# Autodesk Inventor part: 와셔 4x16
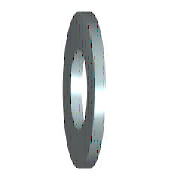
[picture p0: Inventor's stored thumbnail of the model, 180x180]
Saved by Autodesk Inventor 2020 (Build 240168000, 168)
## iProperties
IsCustomPart: 1
Created: 2012-02
Part Number: 와셔 4x16
Material: 강철, 연강
Description: 미터법 평면 와셔
Document SubType Name: Modeling
Standard: ANSI B18.22M
Designer: mduedu
Standard Revision: 1999
Standards Organization: ANSI
Language: ko-KR
Size Designation: 4 W
Categories: <MemberInstance><Categories><Category DisplayName="조임쇠" InternalName="e4da775c-781d-43d5-af7c-5136215cf5a6" Mnemonic="FSTN"><Category DisplayName="와셔" InternalN
Density: 1 g/cm^3
Appearance: 파란색 - 벽 페인트 - 광택
Author: mduedu
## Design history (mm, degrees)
sketch "스케치"
  geometry: C1 r 8 at (0, 0); C2 r 2.35 at (0, 0); 1 further point
  constraints: 2 centre point, 2 coincident
  dimensions: "d0" = 4.7 diameter of C2 (= SD1); "d1" = 16 diameter of C1 (= SD2)
extrude "본체" new body sketch "스케치" distance "d2" = 2.3 (= SD); taper "d3" = 0 deg
workaxis "Work Axis1"
workplane "Work Plane1"
body "Solid1"
other parameters: "SD1" = 4.7 [user parameter; used in 1 equation term], "SD2" = 16 [user parameter; used in 1 equation term], "SD" = 2.3 [user parameter; used in 1 equation term], "d4" = 0, "d5" = 0, "d6" = 0, "d7" = 0, "NND" = 4 [user parameter]
